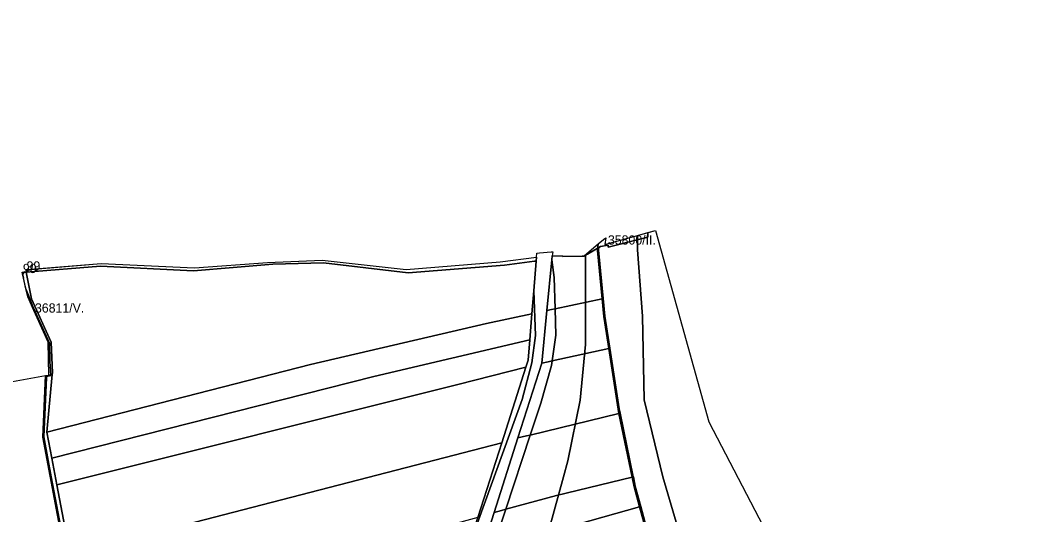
# Model space of a CAD drawing. Extents: x -535894 to -532834, y -1165802 to -1163645.
# Drawn here: x -534170 to -533625, y -1164021 to -1163752 of the extents above; entities that cross this region are included whole.
import ezdxf

# ---------------------------------------------------------------- set-up
doc = ezdxf.new("R2010")
doc.units = 0
for name, color, linetype in [('95560013', 7, 'Continuous'), ('95620013', 7, 'Continuous'), ('95630013', 7, 'Continuous'), ('95640013', 7, 'Continuous'), ('95660013', 7, 'Continuous')]:
    doc.layers.add(name, color=color, linetype=linetype)

msp = doc.modelspace()

# ---------------------------------------------------------------- linework, layer by layer
at = {"layer": '95560013'}
for points in [[(-533856.89, -1163877.14), (-533854.37, -1163903.29), (-533879.91, -1163908.81), (-533880.47, -1163891.74), (-533881.62, -1163882.25), (-533881.4, -1163880.05), (-533866.68, -1163880.24), (-533863.98, -1163879.91), (-533856.45, -1163873.6)], [(-533890.12, -1163882.84), (-533891.13, -1163882.88), (-533907.32, -1163885.02), (-533959.54, -1163889.18), (-534005.5, -1163883.9), (-534033.11, -1163884.59), (-534076.08, -1163888.15), (-534126.63, -1163885.69), (-534166.94, -1163888.88), (-534167.05, -1163887.54), (-534126.29, -1163884.14), (-534075.55, -1163886.63), (-534035.93, -1163883.59), (-534006.23, -1163882.44), (-533960.63, -1163887.47), (-533909.61, -1163883.3), (-533889.94, -1163880.68)], [(-533890.12, -1163882.84), (-533891.45, -1163899.11), (-533892.46, -1163911.51), (-533917.11, -1163916.82), (-534012.6, -1163939), (-534155.71, -1163975.68), (-534152.8, -1163944.4), (-534152.71, -1163943.44), (-534153.31, -1163926.88), (-534163.98, -1163903.4), (-534166.94, -1163888.88), (-534126.63, -1163885.69), (-534076.08, -1163888.15), (-534033.11, -1163884.59), (-534005.5, -1163883.9), (-533959.54, -1163889.18), (-533907.32, -1163885.02), (-533891.13, -1163882.88)], [(-533879.91, -1163908.81), (-533854.37, -1163903.29), (-533853.43, -1163913.02), (-533850.77, -1163930.31), (-533881.54, -1163937.07), (-533879.45, -1163923.12)], [(-533917.11, -1163916.82), (-533892.46, -1163911.51), (-533893.61, -1163925.64), (-533978.28, -1163945.56), (-534153.06, -1163989.73), (-534155.71, -1163975.68), (-534012.6, -1163939)], [(-533894.49, -1163936.59), (-533895.7, -1163940.37), (-533932.68, -1163949.92), (-534150.32, -1164004.31), (-534153.06, -1163989.73), (-533978.28, -1163945.56), (-533893.61, -1163925.64)], [(-533881.54, -1163937.07), (-533850.77, -1163930.31), (-533845.71, -1163963.15), (-533845.21, -1163965.55), (-533893.35, -1163977.24), (-533887.65, -1163959.99), (-533881.92, -1163939.56)], [(-533895.7, -1163940.37), (-533908.87, -1163981.51), (-534085.67, -1164027.32), (-534143.34, -1164041.3), (-534150.32, -1164004.31), (-533932.68, -1163949.92)], [(-533893.35, -1163977.24), (-533845.21, -1163965.55), (-533838.01, -1164000.05), (-533879.17, -1164009.99), (-533906.69, -1164017.55)], [(-533921.81, -1164021.92), (-533995.77, -1164042.33), (-534077.52, -1164062.7), (-534136.93, -1164080.66), (-534142.42, -1164063.29), (-534143.34, -1164041.3), (-534085.67, -1164027.32), (-533908.87, -1163981.51)], [(-533836.92, -1164005.27), (-533833.99, -1164016.17), (-533913.66, -1164038.64), (-533906.69, -1164017.55), (-533879.17, -1164009.99), (-533838.01, -1164000.05)], [(-533829.37, -1164033.3), (-533920.66, -1164059.82), (-533916.23, -1164046.38), (-533913.66, -1164038.64), (-533833.99, -1164016.17)]]:
    msp.add_lwpolyline(points, close=True, dxfattribs=at)
at = {"layer": '95620013'}
msp.add_lwpolyline([(-534427.72, -1163752.13), (-534413.24, -1163763.36), (-534362.72, -1163807.37), (-534355.93, -1163819.24), (-534338.84, -1163838.27), (-534314.16, -1163855.97), (-534296.47, -1163870.97), (-534271.49, -1163905.38), (-534250.57, -1163903.14), (-534241.76, -1163894.34), (-534224.22, -1163957.18), (-534156.41, -1163945.04), (-534157.94, -1163978.43), (-534146.05, -1164041.92), (-534145.18, -1164064.32), (-534137.15, -1164087.2), (-534425.41, -1164026.54)], close=True, dxfattribs=at)
at = {"layer": '95630013'}
msp.add_lwpolyline([(-533614.65, -1164333.34), (-533637.12, -1164313.74), (-533659.7, -1164292.03), (-533688.28, -1164260.76), (-533708.99, -1164234.05), (-533736.29, -1164196.18), (-533760.11, -1164157.23), (-533771.58, -1164135.97), (-533785.98, -1164100.6), (-533807.37, -1164047.78), (-533821.43, -1163999.88), (-533831.47, -1163958.19), (-533832.51, -1163912.75), (-533835.25, -1163876.86), (-533835.15, -1163868.99), (-533825.35, -1163866.3), (-533796.36, -1163970.1), (-533744.41, -1164070.17), (-533714.01, -1164096.6), (-533675.79, -1164164.9), (-533652.75, -1164196.64), (-533615.89, -1164239.81)], dxfattribs=at)
at = {"layer": '95640013'}
for points in [[(-533829.37, -1164033.3), (-533833.99, -1164016.17), (-533836.92, -1164005.27), (-533838.01, -1164000.05), (-533845.21, -1163965.55), (-533845.71, -1163963.15), (-533850.77, -1163930.31), (-533853.43, -1163913.02), (-533854.37, -1163903.29), (-533856.89, -1163877.14), (-533856.45, -1163873.6), (-533853.53, -1163871.16), (-533852.38, -1163870.19), (-533852.91, -1163873.85), (-533850.38, -1163873.16), (-533835.15, -1163868.99), (-533835.25, -1163876.86), (-533832.51, -1163912.75), (-533831.47, -1163958.19), (-533821.43, -1163999.88), (-533807.37, -1164047.78)], [(-533928.41, -1164042.51), (-533897.78, -1163957.92), (-533892.48, -1163938), (-533890.48, -1163923.29), (-533891.45, -1163899.11), (-533890.12, -1163882.84), (-533889.94, -1163880.68), (-533889.77, -1163878.53), (-533888.35, -1163878.41), (-533881.96, -1163877.92), (-533881.19, -1163877.86), (-533881.4, -1163880.05), (-533881.62, -1163882.25), (-533884.29, -1163909.75), (-533887.08, -1163938.28), (-533900.03, -1163978.86), (-533912.94, -1164019.27), (-533919.67, -1164040.34)], [(-534146.05, -1164041.92), (-534157.94, -1163978.43), (-534156.41, -1163945.04), (-534154.6, -1163944.72), (-534152.8, -1163944.4), (-534155.71, -1163975.68), (-534153.06, -1163989.73), (-534150.32, -1164004.31), (-534143.34, -1164041.3)]]:
    msp.add_lwpolyline(points, dxfattribs=at)
for points in [[(-533881.62, -1163882.25), (-533880.47, -1163891.74), (-533879.91, -1163908.81), (-533881.75, -1163909.2), (-533884.29, -1163909.75)], [(-534169.16, -1163888.95), (-534166.94, -1163888.88), (-534163.98, -1163903.4), (-534153.31, -1163926.88), (-534152.71, -1163943.44), (-534152.8, -1163944.4), (-534154.6, -1163944.72), (-534154.95, -1163926.9), (-534166.07, -1163902.27)], [(-533892.46, -1163911.51), (-533891.45, -1163899.11), (-533890.48, -1163923.29), (-533892.48, -1163938), (-533897.78, -1163957.92), (-533928.41, -1164042.51), (-533921.81, -1164021.92), (-533908.87, -1163981.51), (-533895.7, -1163940.37), (-533894.49, -1163936.59), (-533893.61, -1163925.64)], [(-533881.75, -1163909.2), (-533879.91, -1163908.81), (-533879.45, -1163923.12), (-533881.54, -1163937.07), (-533883.64, -1163937.53), (-533887.08, -1163938.28), (-533884.29, -1163909.75)], [(-533883.64, -1163937.53), (-533881.54, -1163937.07), (-533881.92, -1163939.56), (-533887.65, -1163959.99), (-533893.35, -1163977.24), (-533895.38, -1163977.72), (-533900.03, -1163978.86), (-533887.08, -1163938.28)], [(-533895.38, -1163977.72), (-533893.35, -1163977.24), (-533906.69, -1164017.55), (-533908.91, -1164018.16), (-533912.94, -1164019.27), (-533900.03, -1163978.86)], [(-533908.91, -1164018.16), (-533906.69, -1164017.55), (-533913.66, -1164038.64), (-533915.99, -1164039.3), (-533919.67, -1164040.34), (-533912.94, -1164019.27)]]:
    msp.add_lwpolyline(points, close=True, dxfattribs=at)
at = {"layer": '95660013'}
for points in [[(-533856.167, -1163875.563), (-533862.278, -1163879.083), (-533862.503, -1163879.213), (-533863.428, -1163879.746), (-533864.249, -1163880.219), (-533864.98, -1163880.231), (-533875.795, -1163880.402), (-533875.769, -1163880.123), (-533866.68, -1163880.24), (-533863.98, -1163879.91), (-533856.45, -1163873.6), (-533853.53, -1163871.16), (-533852.38, -1163870.19), (-533852.91, -1163873.85), (-533850.38, -1163873.16), (-533835.15, -1163868.99), (-533829.496, -1163867.438), (-533829.601, -1163869.964), (-533834.627, -1163871.207), (-533851.075, -1163875.277), (-533851.075, -1163874.179), (-533855.193, -1163875.002)], [(-534166.675, -1163888.675), (-534166.956, -1163888.683), (-534167.05, -1163887.54), (-534164.382, -1163887.317), (-534163.89, -1163887.698), (-534166.45, -1163887.899), (-534166.395, -1163888.611), (-534166.649, -1163888.63)], [(-534168.86, -1163889.84), (-534168.438, -1163892.06), (-534169.16, -1163888.95), (-534168.411, -1163888.926), (-534168.548, -1163889.001), (-534168.37, -1163889.768)], [(-534161.827, -1163911.667), (-534162.72, -1163909.691), (-534162, -1163911.1)]]:
    msp.add_lwpolyline(points, close=True, dxfattribs=at)
for points in [[(-533828.813, -1164033.1), (-533833.428, -1164015.976), (-533836.361, -1164005.076), (-533837.421, -1164000), (-533837.451, -1163999.854), (-533844.65, -1163965.351), (-533845.148, -1163962.951), (-533850.209, -1163930.114), (-533852.874, -1163912.824), (-533853.814, -1163903.093), (-533856.167, -1163878.726), (-533856.34, -1163876.946), (-533856.305, -1163876.665), (-533856.167, -1163875.563), (-533855.193, -1163875.002), (-533851.075, -1163874.179), (-533851.075, -1163875.277), (-533834.627, -1163871.207), (-533829.601, -1163869.964), (-533829.496, -1163867.438), (-533825.35, -1163866.3), (-533796.36, -1163970.1), (-533744.41, -1164070.17)], [(-533914.47, -1164142.17), (-533875.366, -1164000), (-533872.97, -1163991.29), (-533866.29, -1163958.32), (-533863.428, -1163928.06), (-533863.428, -1163879.746), (-533862.503, -1163879.213), (-533862.278, -1163879.083), (-533856.167, -1163875.563), (-533856.305, -1163876.665), (-533856.34, -1163876.946), (-533856.167, -1163878.726), (-533853.814, -1163903.093), (-533852.874, -1163912.824), (-533850.209, -1163930.114), (-533845.148, -1163962.951), (-533844.65, -1163965.351), (-533837.451, -1163999.854), (-533837.421, -1164000), (-533836.361, -1164005.076), (-533833.428, -1164015.976), (-533828.813, -1164033.1)], [(-534145.49, -1164041.708), (-534153.303, -1164000), (-534154.963, -1163991.136), (-534157.384, -1163978.211), (-534155.912, -1163946.108), (-534155.882, -1163945.429), (-534153.502, -1163945.012), (-534154.189, -1163937.323), (-534154.386, -1163927.396), (-534163.349, -1163907.55), (-534165.3, -1163902.526), (-534165.559, -1163901.864), (-534167.061, -1163897.999), (-534168.438, -1163892.06), (-534168.86, -1163889.84), (-534168.37, -1163889.768), (-534168.548, -1163889.001), (-534168.411, -1163888.926), (-534166.94, -1163888.88), (-534166.956, -1163888.683), (-534166.675, -1163888.675), (-534166.649, -1163888.63), (-534166.395, -1163888.611), (-534166.45, -1163887.899), (-534163.89, -1163887.698), (-534164.382, -1163887.317), (-534126.29, -1163884.14), (-534075.55, -1163886.63), (-534035.93, -1163883.59), (-534006.23, -1163882.44), (-533960.63, -1163887.47), (-533909.61, -1163883.3), (-533889.94, -1163880.68), (-533889.77, -1163878.53), (-533888.35, -1163878.41), (-533881.96, -1163877.92), (-533881.19, -1163877.86), (-533881.4, -1163880.05), (-533875.769, -1163880.123), (-533875.795, -1163880.402), (-533864.98, -1163880.231), (-533864.249, -1163880.219), (-533863.428, -1163879.746), (-533863.428, -1163928.06), (-533866.29, -1163958.32), (-533872.97, -1163991.29), (-533875.366, -1164000), (-533914.47, -1164142.17)], [(-534224.22, -1163957.18), (-534156.41, -1163945.04), (-534154.6, -1163944.72), (-534154.95, -1163926.9), (-534161.827, -1163911.667), (-534162, -1163911.1), (-534162.72, -1163909.691), (-534166.07, -1163902.27), (-534167.061, -1163897.999), (-534165.559, -1163901.864), (-534165.3, -1163902.526), (-534163.349, -1163907.55), (-534154.386, -1163927.396), (-534154.189, -1163937.323), (-534153.502, -1163945.012), (-534155.882, -1163945.429), (-534155.912, -1163946.108), (-534157.384, -1163978.211), (-534154.963, -1163991.136), (-534153.303, -1164000), (-534145.49, -1164041.708)]]:
    msp.add_lwpolyline(points, dxfattribs=at)

# ---------------------------------------------------------------- texts
for s, rotation, p in [('35800/II.', 360, (-533851.211, -1163873.92)), ('99', 0, (-534168.765, -1163889.382)), ('99', 0, (-534166.727, -1163888)), ('36811/V.', 0, (-534162.182, -1163910.819))]:
    msp.add_text(s, height=5, rotation=rotation, dxfattribs=at).set_placement(p)

doc.saveas('drawing.dxf')
